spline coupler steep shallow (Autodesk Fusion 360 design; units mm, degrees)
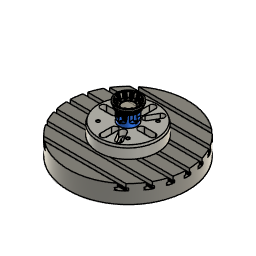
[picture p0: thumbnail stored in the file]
sketch "Sketch1" plane through (0, 0, 0) normal (1, 0, 0) x axis (0, 1, 0)
  line L1 (50.8, 0) -> (0, 0)
  line L2 (50.8, 25.4) -> (50.8, 0)
  line L3 (44.45, 25.4) -> (50.8, 25.4)
  line L4 (37.5164, 6.35) -> (44.45, 25.4)
  line L5 (0, 6.35) -> (37.5164, 6.35)
  line L6 (0, 0) -> (0, 6.35)
  line L7 (50.8, 19.05) -> (50.8, 25.4)
  line L8 (43.8664, 0) -> (50.8, 19.05)
  line L9 (48.0144, 13.7174) -> (48.4888, 12.7)
  line L10 (49.0317, 14.1918) -> (48.0144, 13.7174)
  line L11 (48.7603, 13.4459) -> (48.0144, 13.7174)
  line L12 (46.1776, 6.35) -> (47.0031, 6.35)
  circle C1 centre (48.9975, 12.9372) radius 0.5613
  circle C2 centre (47.0031, 6.35) radius 1.5875
  point P1 (0, 0)
  point P2 (0, 0)
  point P8 (0, 0)
  point P9 (50.8, 19.05)
  point P10 (43.8664, 0)
  point P11 (48.4888, 12.7)
  point P13 (49.0317, 14.1918)
  point P14 (48.7603, 13.4459)
  point P16 (48.4888, 12.7)
  point P17 (48.7603, 13.4459)
  point P18 (47.0031, 6.35)
  point P19 (47.0031, 6.35)
  point P20 (46.1776, 6.35)
  point P3 (50.8, 0)
  point P4 (50.8, 25.4)
  point P7 (0, 6.35)
  point P12 (48.0144, 13.7174)
  point P5 (44.45, 25.4)
  coincident P1 P2
  horizontal L1
  perpendicular L1 L2
  perpendicular L2 L3
  parallel L1 L5
  coincident P1 P8
  vertical L6
  coincident L2 P9
  coincident L1 P10
  parallel L4 L8
  coincident L8 P11
  coincident L8 P13
  perpendicular L9 L10
  equal L9 L10
  coincident L8 P14
  perpendicular L8 L11
  coincident C1 P16
  coincident L8 P16
  coincident P11 P16
  coincident C1 P17
  coincident P14 P17
  tangent L9 C1
  coincident P18 P19
  coincident L8 P20
  horizontal L12
  dimension "d2" = 88.9
  dimension "d3" distance P3 P4 = 25.4
  dimension "d4" angle L3 L4 = 70
  dimension "d5" distance P7 P8 = 6.35
  dimension "d37" distance P4 P9 = 6.35
  dimension "d38" distance P12 P14 = 0.7937
  dimension "d39" distance P10 P11 = 12.7
  dimension "d40" distance P4 P5 = 6.35
  dimension "d43" diameter C2 = 3.175
  dimension "d44" distance L1 P18 = 6.35
  dimension "d45" distance P19 P20 = 0.8255
revolve "Revolve1" sketch "Sketch1" AlongAngle 360
work_plane "WorkPlane1" AlongDistance -3.175
sketch "Sketch2" plane through (0, 0, 22.225) normal (0, 0, 1) x axis (1, 0, 0)
  line L1 (0, 36.9444) -> (0, 0)
  line L2 (3.175, 36.9444) -> (-3.175, 36.9444)
  line L3 (3.175, 32.5535) -> (3.175, 36.9444)
  circle C1 centre (0, 0) radius 43.2944
  circle C2 centre (0, 0) radius 36.9444
  arc A1 centre (10.795, 36.9444) radius 7.62 clockwise from (3.175, 36.9444) to (6.0106, 42.8751)
  arc A2 centre (-10.795, 36.9444) radius 7.62 clockwise from (-6.0106, 42.8751) to (-3.175, 36.9444)
  point P2 (0, 0)
  point P4 (0, 0)
  point P5 (0, 36.9444)
  point P8 (6.0106, 42.8751)
  point P7 (3.175, 36.9444)
  point P13 (-3.175, 36.9444)
  point P12 (-6.0106, 42.8751)
  point P6 (-3.175, 36.9444)
  coincident P2 P4
  coincident C2 P5
  vertical L1
  perpendicular L1 L2
  midpoint P5 L2
  coincident C1 P8
  perpendicular L2 L3
  tangent A1 L3
  symmetric L1 P7 P13
  symmetric L1 P8 P12
  symmetric L1 A1 A2
  dimension "d8" = 6.35
  dimension "d9" distance P6 P7 = 6.35
  dimension "d10" radius A1 = 7.62
sketch "Sketch3" plane through (0, 0, 22.225) normal (0, 0, 1) x axis (1, 0, 0)
sketch "Sketch4" plane through (0, 0, 0) normal (1, 0, 0) x axis (0, 1, 0)
  line L1 (37.5164, 6.35) -> (44.45, 25.4)
  line L2 (-44.45, 25.4) -> (-37.5164, 6.35)
  line L3 (36.9444, 22.225) -> (0, 22.225)
  line L4 (31.1664, 6.35) -> (36.9444, 22.225)
  line L5 (-37.5164, 6.35) -> (37.5164, 6.35)
  point P7 (36.9444, 22.225)
  point P8 (36.9444, 22.225)
  point P9 (31.1664, 6.35)
  coincident P7 P8
  coincident P9 L5
  parallel L1 L4
copy_paste_bodies "CopyPasteBodies2"
sweep "Sweep1" sketch "Sketch2" TwistAngle 0 TaperAngle 0
fillet "Fillet1" sketch "Sketch1" radius 1.5875
fillet "Fillet5" sketch "Sketch1" radius 1.5875
circular_pattern "C-Pattern1" countU 12 TotalAngle 360
fillet "Fillet2" radius 1.5875
fillet "Fillet4" radius 1.5875
sketch "Sketch5" plane through (0, 0, 6.35) normal (0, 0, 1) x axis (-1, 0, 0)
  curve K1 (12.3507, -34.2457) -> (12.1885, -30.8252)
  line L1 (16.5345, -25.1581) -> (13.5203, -26.8984)
  curve K2 (20.6012, -25.9681) -> (23.4823, -27.8189)
  curve K3 (27.8189, -23.4823) -> (25.9681, -20.6012)
  line L2 (26.8984, -13.5203) -> (25.1581, -16.5345)
  curve K4 (30.8252, -12.1885) -> (34.2457, -12.3507)
  curve K5 (35.833, -6.4268) -> (32.7897, -4.8571)
  line L3 (30.0548, 1.7403) -> (30.0548, -1.7403)
  curve K6 (32.7897, 4.8571) -> (35.833, 6.4268)
  curve K7 (34.2457, 12.3507) -> (30.8252, 12.1885)
  line L4 (25.1581, 16.5345) -> (26.8984, 13.5203)
  curve K8 (25.9681, 20.6012) -> (27.8189, 23.4823)
  curve K9 (23.4823, 27.8189) -> (20.6012, 25.9681)
  line L5 (13.5203, 26.8984) -> (16.5345, 25.1581)
  curve K10 (12.1885, 30.8252) -> (12.3507, 34.2457)
  curve K11 (6.4268, 35.833) -> (4.8571, 32.7897)
  line L6 (-1.7403, 30.0548) -> (1.7403, 30.0548)
  curve K12 (-4.8571, 32.7897) -> (-6.4268, 35.833)
  curve K13 (-12.3507, 34.2457) -> (-12.1885, 30.8252)
  line L7 (-16.5345, 25.1581) -> (-13.5203, 26.8984)
  curve K14 (-20.6012, 25.9681) -> (-23.4823, 27.8189)
  curve K15 (-27.8189, 23.4823) -> (-25.9681, 20.6012)
  line L8 (-26.8984, 13.5203) -> (-25.1581, 16.5345)
  curve K16 (-30.8252, 12.1885) -> (-34.2457, 12.3507)
  curve K17 (-35.833, 6.4268) -> (-32.7897, 4.8571)
  line L9 (-30.0548, -1.7403) -> (-30.0548, 1.7403)
  curve K18 (-32.7897, -4.8571) -> (-35.833, -6.4268)
  curve K19 (-34.2457, -12.3507) -> (-30.8252, -12.1885)
  line L10 (-25.1581, -16.5345) -> (-26.8984, -13.5203)
  curve K20 (-25.9681, -20.6012) -> (-27.8189, -23.4823)
  curve K21 (-23.4823, -27.8189) -> (-20.6012, -25.9681)
  line L11 (-13.5203, -26.8984) -> (-16.5345, -25.1581)
  curve K22 (-12.1885, -30.8252) -> (-12.3507, -34.2457)
  curve K23 (-6.4268, -35.833) -> (-4.8571, -32.7897)
  line L12 (1.7403, -30.0548) -> (-1.7403, -30.0548)
  curve K24 (4.8571, -32.7897) -> (6.4268, -35.833)
  closed curve K25 centre (15.2096, -29.8245)
  closed curve K26 centre (18.2239, -28.0842)
  arc A1 centre (0, 0) radius 36.4048 clockwise from (27.8189, -23.4823) to (23.4823, -27.8189)
  closed curve K27 centre (28.0842, -18.2239)
  closed curve K28 centre (29.8245, -15.2096)
  arc A2 centre (0, 0) radius 36.4048 clockwise from (35.833, -6.4268) to (34.2457, -12.3507)
  closed curve K29 centre (33.4336, -1.7403)
  closed curve K30 centre (33.4336, 1.7403)
  arc A3 centre (0, 0) radius 36.4048 clockwise from (34.2457, 12.3507) to (35.833, 6.4268)
  closed curve K31 centre (29.8245, 15.2096)
  closed curve K32 centre (28.0842, 18.2239)
  arc A4 centre (0, 0) radius 36.4048 clockwise from (23.4823, 27.8189) to (27.8189, 23.4823)
  closed curve K33 centre (18.2239, 28.0842)
  closed curve K34 centre (15.2096, 29.8245)
  arc A5 centre (0, 0) radius 36.4048 clockwise from (6.4268, 35.833) to (12.3507, 34.2457)
  closed curve K35 centre (1.7403, 33.4336)
  closed curve K36 centre (-1.7403, 33.4336)
  arc A6 centre (0, 0) radius 36.4048 clockwise from (-12.3507, 34.2457) to (-6.4268, 35.833)
  closed curve K37 centre (-15.2096, 29.8245)
  closed curve K38 centre (-18.2239, 28.0842)
  arc A7 centre (0, 0) radius 36.4048 clockwise from (-27.8189, 23.4823) to (-23.4823, 27.8189)
  closed curve K39 centre (-28.0842, 18.2239)
  closed curve K40 centre (-29.8245, 15.2096)
  arc A8 centre (0, 0) radius 36.4048 clockwise from (-35.833, 6.4268) to (-34.2457, 12.3507)
  closed curve K41 centre (-33.4336, 1.7403)
  closed curve K42 centre (-33.4336, -1.7403)
  arc A9 centre (0, 0) radius 36.4048 clockwise from (-34.2457, -12.3507) to (-35.833, -6.4268)
  closed curve K43 centre (-29.8245, -15.2096)
  closed curve K44 centre (-28.0842, -18.2239)
  arc A10 centre (0, 0) radius 36.4048 clockwise from (-23.4823, -27.8189) to (-27.8189, -23.4823)
  closed curve K45 centre (-18.2239, -28.0842)
  closed curve K46 centre (-15.2096, -29.8245)
  arc A11 centre (0, 0) radius 36.4048 clockwise from (-6.4268, -35.833) to (-12.3507, -34.2457)
  closed curve K47 centre (-1.7403, -33.4336)
  closed curve K48 centre (1.7403, -33.4336)
  arc A12 centre (0, 0) radius 36.4048 clockwise from (12.3507, -34.2457) to (6.4268, -35.833)
  circle C1 centre (0, 0) radius 25.4
  concentric A1 C1
  dimension "d29" diameter C1 = 50.8
extrude "Extrude1" cut sketch "Sketch5" profile of C1 against normal blind 3.175
chamfer "Chamfer1" sketch "Sketch1" distance 0.7937
fillet "Fillet6" sketch "Sketch1" radius 1.5875
delete_face "DeleteFace1"
delete_face "DeleteFace2"
delete_face "DeleteFace3"
derived_base_feature "Derived Base Feature1" bodies "Dovetail"
move "Move1"
offset_faces "OffsetFaces1" distance -25.4
move "Move2"
align "Align1"
combine "Combine2" bodies "Dovetail"
derived_base_feature "Derived Base Feature1" bodies "Body1"
base_feature "Base Feature1"
joint "Assemble1" alignAngle 0 alignOffsetX 0 named "d2_1" alignOffsetY 0 named "d3_1" alignOffsetZ 0 named "d4_1"
base_feature "Base Feature1" bodies "Body1", "Body2", "Body3", "Body4", "Body5", "Body6"
joint "Assemble2" alignAngle 0 named "d5_1" alignOffsetX 0 named "d6_1" alignOffsetY 0 named "d7_1" alignOffsetZ 0 named "d8_1"
joint "Assemble1" alignAngle 0 alignOffsetX 0 alignOffsetY 0 alignOffsetZ 0
sketch "Sketch7" plane through (0, 0, 0) normal (1, 0, 0) x axis (0, 1, 0)
  line L1 (-251.1903, -101.5746) -> (-198.6319, -101.5746)
  point P1 (0, 0)
  point P2 (0, -355.5746)
  vertical P1 P2
  dimension "d51" distance P2 L1 = 254
work_point "WorkPoint1"
sketch "Dovetail" plane through (0, 0, 0) normal (1, 0, 0) x axis (0, 1, 0)
  line L1 (-18.5336, -2.3876) -> (-17.1551, 0)
  line L2 (-18.5336, -3.1496) -> (-18.5336, -2.3876)
  line L3 (-23.5051, 0) -> (-17.1551, 0)
  line L4 (-23.5051, -50.8) -> (-23.5051, 0)
  line L5 (-18.5336, -50.8) -> (-23.5051, -50.8)
  line L6 (-18.5336, -3.1496) -> (-18.5336, -50.8)
  point P2 (-17.1551, 0)
  point P6 (-17.1551, 0)
  point P5 (-18.5336, -3.1496)
  point P10 (-18.5336, -3.1496)
  point P7 (-23.5051, 0)
  point P8 (-23.5051, -50.8)
  coincident P2 P6
  horizontal L3
  perpendicular L3 L4
  perpendicular L4 L5
  coincident P5 P10
  vertical L6
  dimension "d52" = 12.7
  dimension "d53" distance P7 P8 = 50.8
sketch "Sketch9" plane through (0, 0, 0) normal (1, 0, 0) x axis (0, 1, 0)
  line L1 (31.5465, 7.3945) -> (36.5642, 21.1805)
revolve "Revolve3" AlongAngle 360
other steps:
base_feature "Base Feature2" bodies "Stock"
joint_origin "JointOrigin1"
create_component "CreateComponent1"
joint_origin "JointOrigin1"
create_component "CreateComponent2"
create_component "CreateComponent2"
create_component "CreateComponent3"
named bodies: "Part", "Stock", "Dovetail", "Body1", "Body2", "Body3", "Body4", "Body5", "Body6"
